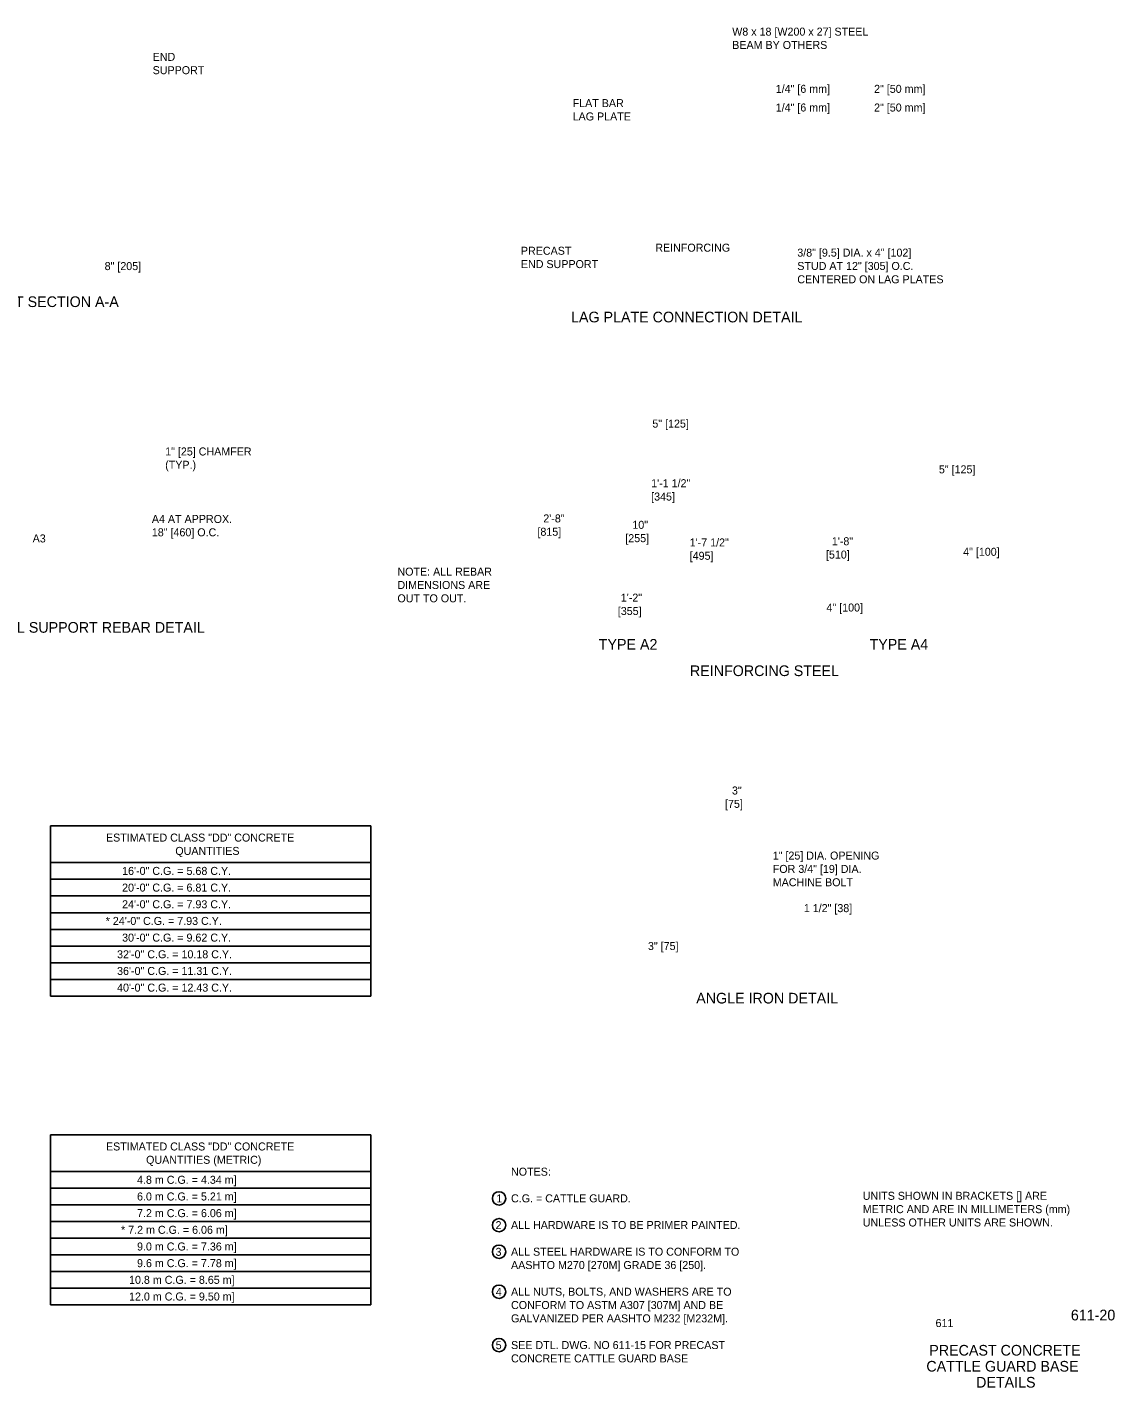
# Model space of a CAD drawing. Extents: x 49987.2 to 50044, y 49982.5 to 50011.4.
# Drawn here: x 50035.8 to 50043.96, y 49988.31 to 49998.52 of the extents above; entities that cross this region are included whole.
import ezdxf

# ---------------------------------------------------------------- set-up
doc = ezdxf.new("R2010")
doc.units = 0
doc.layers.add('Default', color=7, linetype='Continuous')
doc.layers.add('Level 2', color=7, linetype='Continuous')

msp = doc.modelspace()

# ---------------------------------------------------------------- linework, layer by layer
at = {"layer": 'Default'}
for centre in [(50039.338, 49989.734), (50039.338, 49989.533), (50039.338, 49989.334), (50039.338, 49989.034), (50039.338, 49988.634)]:
    msp.add_circle(centre, 0.05, dxfattribs=at)
at = {"layer": 'Level 2'}
for p, q in [((50038.377, 49992.526), (50035.974, 49992.526)), ((50035.974, 49992.526), (50035.974, 49991.251)), ((50038.377, 49991.251), (50038.377, 49992.526)), ((50038.377, 49992.251), (50035.974, 49992.251)), ((50038.377, 49992.126), (50035.974, 49992.126)), ((50038.377, 49992.001), (50035.974, 49992.001)), ((50038.377, 49991.876), (50035.974, 49991.876)), ((50038.377, 49991.751), (50035.974, 49991.751)), ((50038.377, 49991.626), (50035.974, 49991.626)), ((50038.377, 49991.501), (50035.974, 49991.501)), ((50038.377, 49991.376), (50035.974, 49991.376)), ((50038.377, 49991.251), (50035.974, 49991.251)), ((50038.377, 49990.21), (50035.974, 49990.21)), ((50035.974, 49990.21), (50035.974, 49988.935)), ((50038.377, 49988.935), (50038.377, 49990.21)), ((50038.377, 49989.935), (50035.974, 49989.935)), ((50038.377, 49989.81), (50035.974, 49989.81)), ((50038.377, 49989.685), (50035.974, 49989.685)), ((50038.377, 49989.56), (50035.974, 49989.56)), ((50038.377, 49989.435), (50035.974, 49989.435)), ((50038.377, 49989.31), (50035.974, 49989.31)), ((50038.377, 49989.185), (50035.974, 49989.185)), ((50038.377, 49989.06), (50035.974, 49989.06)), ((50038.377, 49988.935), (50035.974, 49988.935))]:
    msp.add_line(p, q, dxfattribs=at)

# ---------------------------------------------------------------- texts
at = {"layer": 'Default'}
for s, p in [('1', (50039.318, 49989.703)), ('2', (50039.312, 49989.503)), ('3', (50039.312, 49989.303)), ('4', (50039.314, 49989.003)), ('5', (50039.313, 49988.603))]:
    msp.add_text(s, height=0.06, dxfattribs=at).set_placement(p)
at = {"layer": 'Level 2'}
for s, height, p in [('W8 x 18 [W200 x 27] STEEL', 0.06, (50041.087, 49998.452)), ('END', 0.06, (50036.74, 49998.263)), ('BEAM BY OTHERS', 0.06, (50041.087, 49998.352)), ('SUPPORT', 0.06, (50036.74, 49998.163)), ('1/4" [6 mm]', 0.06, (50041.413, 49998.023)), ('2" [50 mm]', 0.06, (50042.151, 49998.023)), ('FLAT BAR', 0.06, (50039.89, 49997.916)), ('1/4" [6 mm]', 0.06, (50041.413, 49997.883)), ('2" [50 mm]', 0.06, (50042.151, 49997.883)), ('LAG PLATE', 0.06, (50039.89, 49997.816)), ('REINFORCING', 0.06, (50040.51, 49996.832)), ('PRECAST', 0.06, (50039.502, 49996.809)), ('3/8" [9.5] DIA. x 4" [102]', 0.06, (50041.575, 49996.795)), ('8" [205]', 0.06, (50036.38, 49996.694)), ('END SUPPORT', 0.06, (50039.502, 49996.709)), ('STUD AT 12" [305] O.C.', 0.06, (50041.575, 49996.695)), ('CENTERED ON LAG PLATES', 0.06, (50041.575, 49996.595)), ('END SUPPORT SECTION A-A', 0.08, (50035, 49996.417)), ('LAG PLATE CONNECTION DETAIL', 0.08, (50039.878, 49996.302)), ('5" [125]', 0.06, (50040.488, 49995.513)), ('1" [25] CHAMFER', 0.06, (50036.834, 49995.304)), ('(TYP.)', 0.06, (50036.834, 49995.204)), ('5" [125]', 0.06, (50042.637, 49995.17)), ('1\'-1 1/2"', 0.06, (50040.479, 49995.066)), ('[345]', 0.06, (50040.479, 49994.966)), ('A4 AT APPROX.', 0.06, (50036.734, 49994.798)), ('2\'-8"', 0.06, (50039.67, 49994.802)), ('18" [460] O.C.', 0.06, (50036.734, 49994.698)), ('[815]', 0.06, (50039.626, 49994.702)), ('10"', 0.06, (50040.338, 49994.754)), ('A3', 0.06, (50035.84, 49994.652)), ('[255]', 0.06, (50040.285, 49994.654)), ('1\'-7 1/2"', 0.06, (50040.768, 49994.622)), ('1\'-8"', 0.06, (50041.834, 49994.631)), ('[495]', 0.06, (50040.768, 49994.522)), ('[510]', 0.06, (50041.79, 49994.531)), ('4" [100]', 0.06, (50042.819, 49994.552)), ('NOTE: ALL REBAR', 0.06, (50038.576, 49994.403)), ('DIMENSIONS ARE', 0.06, (50038.576, 49994.303)), ('OUT TO OUT.', 0.06, (50038.576, 49994.203)), ('1\'-2"', 0.06, (50040.251, 49994.208)), ('[355]', 0.06, (50040.229, 49994.108)), ('4" [100]', 0.06, (50041.794, 49994.134)), ('LATERAL SUPPORT REBAR DETAIL', 0.08, (50035.306, 49993.975)), ('TYPE A2', 0.08, (50040.086, 49993.848)), ('TYPE A4', 0.08, (50042.117, 49993.848)), ('REINFORCING STEEL', 0.08, (50040.77, 49993.65)), ('3"', 0.06, (50041.085, 49992.762)), ('[75]', 0.06, (50041.033, 49992.662)), ('ESTIMATED CLASS "DD" CONCRETE', 0.06, (50036.39, 49992.409)), ('QUANTITIES', 0.06, (50036.91, 49992.309)), ('1" [25] DIA. OPENING', 0.06, (50041.391, 49992.274)), ('16\'-0" C.G. = 5.68 C.Y.', 0.06, (50036.511, 49992.159)), ('FOR 3/4" [19] DIA.', 0.06, (50041.391, 49992.174)), ('MACHINE BOLT', 0.06, (50041.391, 49992.074)), ('20\'-0" C.G. = 6.81 C.Y.', 0.06, (50036.511, 49992.034)), ('24\'-0" C.G. = 7.93 C.Y.', 0.06, (50036.511, 49991.909)), ('1 1/2" [38]', 0.06, (50041.624, 49991.88)), ('* 24\'-0" C.G. = 7.93 C.Y.', 0.06, (50036.388, 49991.784)), ('30\'-0" C.G. = 9.62 C.Y.', 0.06, (50036.511, 49991.659)), (' 32\'-0" C.G. = 10.18 C.Y.', 0.06, (50036.451, 49991.534)), ('3" [75]', 0.06, (50040.455, 49991.596)), (' 36\'-0" C.G. = 11.31 C.Y.', 0.06, (50036.451, 49991.409)), (' 40\'-0" C.G. = 12.43 C.Y.', 0.06, (50036.451, 49991.284)), ('ANGLE IRON DETAIL', 0.08, (50040.817, 49991.195)), ('ESTIMATED CLASS "DD" CONCRETE', 0.06, (50036.39, 49990.093)), ('QUANTITIES (METRIC)', 0.06, (50036.691, 49989.993)), ('NOTES:', 0.06, (50039.428, 49989.904)), ('4.8 m C.G. = 4.34 m]', 0.06, (50036.623, 49989.843)), ('6.0 m C.G. = 5.21 m]', 0.06, (50036.623, 49989.718)), ('C.G. = CATTLE GUARD.', 0.06, (50039.428, 49989.704)), ('UNITS SHOWN IN BRACKETS [] ARE ', 0.06, (50042.066, 49989.723)), ('7.2 m C.G. = 6.06 m]', 0.06, (50036.623, 49989.593)), ('METRIC AND ARE IN MILLIMETERS (mm) ', 0.06, (50042.066, 49989.623)), ('ALL HARDWARE IS TO BE PRIMER PAINTED.', 0.06, (50039.428, 49989.504)), ('UNLESS OTHER UNITS ARE SHOWN.', 0.06, (50042.066, 49989.523)), ('* 7.2 m C.G. = 6.06 m]', 0.06, (50036.503, 49989.468)), ('9.0 m C.G. = 7.36 m]', 0.06, (50036.623, 49989.343)), ('ALL STEEL HARDWARE IS TO CONFORM TO', 0.06, (50039.428, 49989.304)), ('9.6 m C.G. = 7.78 m]', 0.06, (50036.623, 49989.218)), ('AASHTO M270 [270M] GRADE 36 [250].', 0.06, (50039.428, 49989.204)), ('10.8 m C.G. = 8.65 m]', 0.06, (50036.563, 49989.093)), ('ALL NUTS, BOLTS, AND WASHERS ARE TO', 0.06, (50039.428, 49989.004)), ('12.0 m C.G. = 9.50 m]', 0.06, (50036.563, 49988.968)), ('CONFORM TO ASTM A307 [307M] AND BE ', 0.06, (50039.428, 49988.904)), ('GALVANIZED PER AASHTO M232 [M232M].', 0.06, (50039.428, 49988.804)), ('611-20', 0.08, (50043.627, 49988.819)), ('611', 0.06, (50042.612, 49988.769)), ('SEE DTL. DWG. NO 611-15 FOR PRECAST', 0.06, (50039.428, 49988.604)), ('PRECAST CONCRETE', 0.08, (50042.565, 49988.555)), ('CONCRETE CATTLE GUARD BASE', 0.06, (50039.428, 49988.504)), ('CATTLE GUARD BASE', 0.08, (50042.543, 49988.435)), ('DETAILS', 0.08, (50042.916, 49988.315))]:
    msp.add_text(s, height=height, dxfattribs=at).set_placement(p)

doc.saveas('drawing.dxf')
